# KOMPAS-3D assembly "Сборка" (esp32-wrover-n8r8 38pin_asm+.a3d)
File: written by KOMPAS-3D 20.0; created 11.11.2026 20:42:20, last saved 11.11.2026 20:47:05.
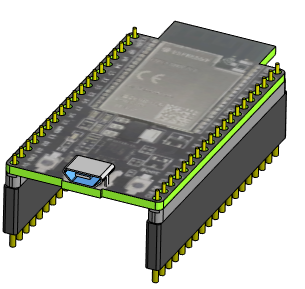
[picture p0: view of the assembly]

Document properties: Полное имя файла: D:\RicWork\Project-EPS32\box_compas\esp32\esp32-wrover-n8r8 38pin_asm+.a3d

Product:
- Part/product: Сборка
    Масса: 0.0330708
  - Component [assembly]: Сборка  | Масса: 0.021523; source file: esp32-wrover-n8r8 38pin_asm.a3d
  - Component [detail]: Деталь  | qty 2  | Масса: 0.00577391; source file: ..\разъемы\pbs_19.m3d

Referenced files in D:\RicWork\Project-EPS32\box_compas\esp32\: esp32-wrover-n8r8 38pin_asm.a3d
Referenced files in D:\RicWork\Project-EPS32\box_compas\разъемы\: pbs_19.m3d
Referenced files in D:\myProjects\Progect_esp32\box_compas\разъемы\: pbs_19.m3d
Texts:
  Деталь (1)
  Деталь (2)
